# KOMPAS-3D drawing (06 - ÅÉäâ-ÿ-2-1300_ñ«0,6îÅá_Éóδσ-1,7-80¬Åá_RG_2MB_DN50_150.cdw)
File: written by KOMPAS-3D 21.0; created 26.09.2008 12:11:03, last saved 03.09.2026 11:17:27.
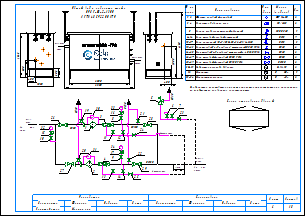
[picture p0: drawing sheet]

Sheets 1-2: A3, landscape

Document properties: Наименование: Макро:21; Автор: RaskoAdmin; Форматы листов документа: 2xA3; Полное имя файла: \\UR38nt01\Departments\КТО\КБ ПУРДГ\Заявки\Прайс-лист на типовые шкафы ГРПШ\ПРДГ_стандарт_20_03_2026\ПРДГ с RG_2MB\ПРДГ-Ш-2-1300_до0,6МПа_Рвых-1,7-80кПа_RG_2MB_DN50_150.cdw

Title block, sheet 1: Наименование: Пункт учета газа / ПУГ-Ш-400-Р / ЛГТИ.485922.001ТУ; designation: ЛГТИ.03.4411141; sheet number: 1; Количество листов документа: 2; organisation: ООО "ЭЛЬСТЕР Газэлектроника"; Форматы листов документа: A3; stored path: C:\Рабочие документы\Компас\ПУГ\Схема.cdw; Разработал: Устинов; Проверил: Кошкин; Утвердил: Кошкин
Title block, sheet 2: sheet number: 2; stored path: D:\Рабочие документы\Заявки\ПУРДГ\ПУРДГ-ШУЭО-2-100-Р 4411220.cdw; designation, second copy: ЛГТИ.03.4411141-

Views: Вид 1, Вид 2
Referenced files: wcvoit.frw
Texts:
  Normal
  Вход
  газа
  PDI
  Выход
  Р=     кПа
  DN150
  DN50
  DN20
  Импульс DN20
  ≥5DN
  HYSWLongFangSong
  № на
  схеме
  Усл.
  обозн.
  Марка
  (модель)
  Кол.
  Фильтр газовый фланцевый
  ФГ 16-50
  Регулятор давления газа
  RG/2MB
  Клапан предохранительный сбросной
  КПС DN20
  Кран шаровой газовый латунный
  DN15
  Кран кнопочный VE-РАСКО-НЗ-1,6-G1/2-М20
  Кран шаровой "под приварку" штуцерный DN20 PN16
  Кран шаровой "под приварку" штуцерный п/п DN20 PN16
  Кран шаровой фланцевый DN50 PN16
  Кран шаровой фланцевый DN150 PN16
  Индикатор перепада давления
  Delta 15
  Манометр
  Манометр-напоромер
  0...     МПа
  0...     кПа
  Общий вид и габариты шкафа
  ПРДГ-Ш-2-1300
  Выход газа
  Вход газа
  Схема открывания дверей
  Р=        МПа
  logo-rasko-ge.png
  Предприятие изготовитель может заменять комплектующие на аналогичные,
  не ухудшающие заявленных характеристик.
  Должность
  Конструктор
  Фамилия
  Подпись
  Дата
  Согласовано
  Максимкин
  Лист
  Листов
  POLYLINE_STYLE_0.18_RGB_0_0_0
  POLYLINE_STYLE_0.50_RGB_0_0_0
  POLYLINE_STYLE_0.34_RGB_0_0_0
  PHANTOM_RGB_0_0_0_SC_1_THICK_0.18
  K5LT_THIN_RGB_0_0_0_THICK_0.18
  K5LT32769_RGB_0_0_0_THICK_0.18
  K5LT12_RGB_0_0_0_SC_1_THICK_0.18
  K5LT_DASHED_RGB_0_0_0_SC_1_THICK_0.18
  ACISOTGL_RGB_0_0_0_SC_0.8_THICK_0.25
  CONTINUOUS_RGB_0_127_31_THICK_0.3
  CONTINUOUS_RGB_0_0_255_THICK_0.35
  CONTINUOUS_RGB_255_0_0_THICK_0.35
  POLYLINE_STYLE_0.25_RGB_0_0_0
  CONTINUOUS_RGB_0_0_0_THICK_0.5
  POLYLINE_STYLE_0.35_RGB_0_0_255
  CONTINUOUS_RGB_0_0_0_THICK_0.4
  CONTINUOUS_RGB_0_0_0_THICK_0.35
  Без оформления
Dimensions and other numbers on the sheet: 1; 2; 3; 4; 5; 10; 27; 28; 29; 23; 8; 12; 19; 20; 21; 22; 25; 24; 30; 31; 15; 16; 26; 6; 7; 11; 14; 13; 33; 1, 2; 3, 4; 6-14; 9; 15-17; 18-23; 24-25; 26-27; 28-29; 30-31; 32; 33-34; 400; 1050; 500; 305; 2500; 1565; 2800; 17; 34; 1000; 4130; 18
